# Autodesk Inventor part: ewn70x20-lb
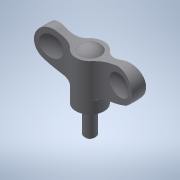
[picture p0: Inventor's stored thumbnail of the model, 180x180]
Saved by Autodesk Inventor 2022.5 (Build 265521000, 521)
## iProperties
Created: 2016-12
Part Number: ewn70x20-lb
Material: 一般
Document SubType Name: Modeling
Designer: imaocorp
Density: 1 g/cm^3
Appearance: 既定
Author: imaocorp
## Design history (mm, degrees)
node "ewn70x20-lb.x_t1"
node "ewn70x20-lb"
node "Base1"
